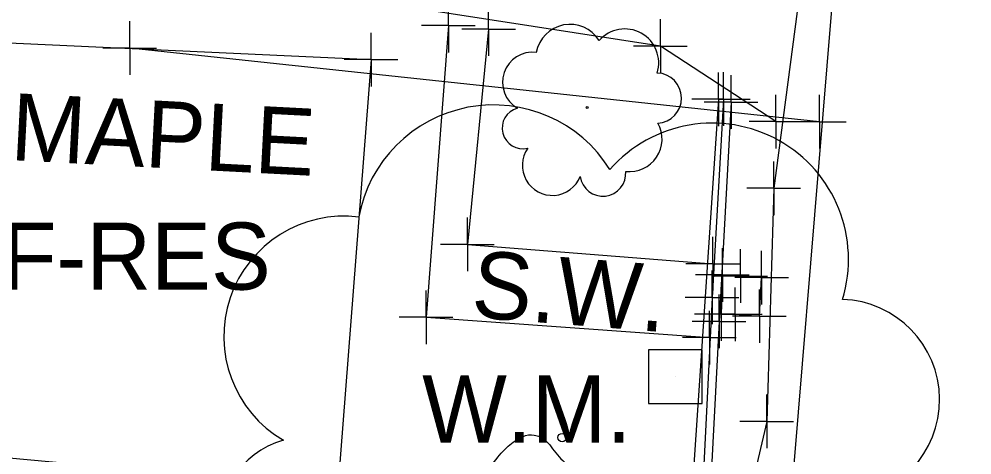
# Model space of a CAD drawing. Extents: x 0 to 1944463, y 0 to 420651.
# Drawn here: x 1943328.1 to 1943399.2, y 417456.9 to 417489.4 of the extents above; entities that cross this region are included whole.
import ezdxf

# ---------------------------------------------------------------- set-up
doc = ezdxf.new("R2010")
doc.units = 0
for name, color, linetype in [('SUR - DTM - Breaklines', 7, 'Continuous'), ('SUR - DTM - Breaklines - Points - Locators', 7, 'Continuous'), ('SUR - NON-TRAN - Buildings', 7, 'Continuous'), ('SUR - NON-TRAN - Buildings - Points - Locators', 7, 'Continuous'), ('SUR - NON-TRAN - Buildings Text', 7, 'Continuous'), ('SUR - NON-TRAN - Features', 7, 'Continuous'), ('SUR - NON-TRAN - Features - Points - Locators', 7, 'Continuous'), ('SUR - NON-TRAN - Features Text', 7, 'Continuous'), ('SUR - PROPERTY - Property Lines', 7, 'Continuous'), ('SUR - TRAN - Features', 7, 'Continuous'), ('SUR - TRAN - Features - Points - Locators', 7, 'Continuous'), ('SUR - TRAN - Roads', 7, 'Continuous'), ('SUR - UTL - Gas', 7, 'Continuous'), ('SUR - UTL - Gas - Points - Locators', 7, 'Continuous'), ('SUR - UTL - Water', 7, 'Continuous'), ('SUR - UTL - Water Text', 7, 'Continuous'), ('SUR - VEG - Features', 7, 'Continuous'), ('SUR - VEG - Features Text', 7, 'Continuous')]:
    doc.layers.add(name, color=color, linetype=linetype)

msp = doc.modelspace()

# ---------------------------------------------------------------- linework, layer by layer
at = {"layer": 'SUR - DTM - Breaklines'}
msp.add_lwpolyline([(1943380.642, 417483.427), (1943379.797, 417468.639), (1943378.803, 417448.68), (1943377.528, 417435.038), (1943376.817, 417428.3), (1943372.837, 417417.332), (1943366.556, 417409.532), (1943358.706, 417403.977), (1943345.201, 417400.148), (1943336.847, 417400.463), (1943331.897, 417401.687), (1943333.202, 417404.643), (1943334.476, 417407.618), (1943330.251, 417411.185), (1943325.276, 417416.517)], dxfattribs=at)
at = {"layer": 'SUR - DTM - Breaklines - Points - Locators'}
for p, q in [((1943380.642, 417483.427), (1943380.642, 417485.427)), ((1943380.642, 417483.427), (1943378.642, 417483.427)), ((1943380.642, 417483.427), (1943382.642, 417483.427)), ((1943380.642, 417483.427), (1943380.642, 417481.427)), ((1943379.797, 417468.639), (1943379.797, 417470.639)), ((1943379.797, 417468.639), (1943377.797, 417468.639)), ((1943379.797, 417468.639), (1943381.797, 417468.639)), ((1943379.797, 417468.639), (1943379.797, 417466.639))]:
    msp.add_line(p, q, dxfattribs=at)
at = {"layer": 'SUR - NON-TRAN - Buildings'}
msp.add_lwpolyline([(1943316.019, 417488.155), (1943354.37, 417486.375), (1943351.907, 417454.397), (1943314.182, 417457.873)], close=True, dxfattribs=at)
at = {"layer": 'SUR - NON-TRAN - Buildings - Points - Locators'}
for q in [(1943354.37, 417488.375), (1943352.37, 417486.375), (1943356.37, 417486.375), (1943354.37, 417484.375)]:
    msp.add_line((1943354.37, 417486.375), q, dxfattribs=at)
at = {"layer": 'SUR - NON-TRAN - Features'}
for points in [[(1943360.144, 417488.914), (1943358.476, 417467.167), (1943379.591, 417465.646)], [(1943363.137, 417488.646), (1943361.555, 417472.59), (1943379.845, 417471.153)], [(1943380.276, 417483.415), (1943377.045, 417435.54)]]:
    msp.add_lwpolyline(points, dxfattribs=at)
msp.add_lwpolyline([(1943380.481, 417467.403), (1943381.521, 417467.388), (1943383.315, 417467.244), (1943383.486, 417470.125), (1943381.918, 417470.238), (1943380.561, 417470.323)], close=True, dxfattribs=at)
at = {"layer": 'SUR - NON-TRAN - Features - Points - Locators'}
for p, q in [((1943360.144, 417488.914), (1943360.144, 417490.914)), ((1943363.137, 417488.646), (1943363.137, 417490.646)), ((1943360.144, 417488.914), (1943358.144, 417488.914)), ((1943360.144, 417488.914), (1943362.144, 417488.914)), ((1943360.144, 417488.914), (1943360.144, 417486.914)), ((1943363.137, 417488.646), (1943361.137, 417488.646)), ((1943363.137, 417488.646), (1943365.137, 417488.646)), ((1943363.137, 417488.646), (1943363.137, 417486.646)), ((1943380.276, 417483.415), (1943380.276, 417485.415)), ((1943380.276, 417483.415), (1943378.276, 417483.415)), ((1943380.276, 417483.415), (1943382.276, 417483.415)), ((1943380.276, 417483.415), (1943380.276, 417481.415)), ((1943361.555, 417472.59), (1943361.555, 417474.59)), ((1943361.555, 417472.59), (1943359.555, 417472.59)), ((1943361.555, 417472.59), (1943363.555, 417472.59)), ((1943361.555, 417472.59), (1943361.555, 417470.59)), ((1943379.845, 417471.153), (1943379.845, 417473.153)), ((1943380.561, 417470.323), (1943380.561, 417472.323)), ((1943381.918, 417470.238), (1943381.918, 417472.238)), ((1943383.486, 417470.125), (1943383.486, 417472.125)), ((1943379.845, 417471.153), (1943377.845, 417471.153)), ((1943379.845, 417471.153), (1943381.845, 417471.153)), ((1943379.845, 417471.153), (1943379.845, 417469.153)), ((1943380.561, 417470.323), (1943378.561, 417470.323)), ((1943381.918, 417470.238), (1943379.918, 417470.238)), ((1943380.561, 417470.323), (1943382.561, 417470.323)), ((1943380.561, 417470.323), (1943380.561, 417468.323)), ((1943383.486, 417470.125), (1943381.486, 417470.125)), ((1943381.918, 417470.238), (1943383.918, 417470.238)), ((1943381.918, 417470.238), (1943381.918, 417468.238)), ((1943383.486, 417470.125), (1943385.486, 417470.125)), ((1943383.486, 417470.125), (1943383.486, 417468.125)), ((1943358.476, 417467.167), (1943358.476, 417469.167)), ((1943380.481, 417467.403), (1943380.481, 417469.403)), ((1943381.521, 417467.388), (1943381.521, 417469.388)), ((1943383.315, 417467.244), (1943383.315, 417469.244)), ((1943379.591, 417465.646), (1943379.591, 417467.646)), ((1943358.476, 417467.167), (1943356.476, 417467.167)), ((1943358.476, 417467.167), (1943360.476, 417467.167)), ((1943358.476, 417467.167), (1943358.476, 417465.167)), ((1943380.481, 417467.403), (1943378.481, 417467.403)), ((1943381.521, 417467.388), (1943379.521, 417467.388)), ((1943380.481, 417467.403), (1943382.481, 417467.403)), ((1943380.481, 417467.403), (1943380.481, 417465.403)), ((1943383.315, 417467.244), (1943381.315, 417467.244)), ((1943381.521, 417467.388), (1943383.521, 417467.388)), ((1943381.521, 417467.388), (1943381.521, 417465.388)), ((1943383.315, 417467.244), (1943385.315, 417467.244)), ((1943383.315, 417467.244), (1943383.315, 417465.244)), ((1943379.591, 417465.646), (1943377.591, 417465.646)), ((1943379.591, 417465.646), (1943381.591, 417465.646)), ((1943379.591, 417465.646), (1943379.591, 417463.646))]:
    msp.add_line(p, q, dxfattribs=at)
at = {"layer": 'SUR - NON-TRAN - Features Text'}
msp.add_open_spline([(1943358.733, 417447.376), (1943364.885, 417461.676), (1943370.847, 417453.152), (1943378.417, 417456.17)], degree=2, dxfattribs=at)
at = {"layer": 'SUR - PROPERTY - Property Lines'}
for p, q in [((1943384.392, 417476.781), (1943384.392, 417478.781)), ((1943384.392, 417476.781), (1943382.392, 417476.781)), ((1943384.392, 417476.781), (1943386.392, 417476.781)), ((1943384.392, 417476.781), (1943384.392, 417474.781)), ((1943383.862, 417459.391), (1943383.862, 417461.391)), ((1943383.862, 417459.391), (1943381.862, 417459.391)), ((1943383.862, 417459.391), (1943385.862, 417459.391)), ((1943383.862, 417459.391), (1943383.862, 417457.391))]:
    msp.add_line(p, q, dxfattribs=at)
at = {"layer": 'SUR - TRAN - Features'}
for points in [[(1943384.554, 417481.747), (1943375.941, 417487.388), (1943318.331, 417496.289), (1943305.868, 417491.574)], [(1943381.209, 417483.206), (1943380.319, 417466.847), (1943379.372, 417448.773), (1943378.142, 417434.863), (1943377.392, 417428.08), (1943373.406, 417417.226), (1943366.92, 417409.033), (1943358.987, 417403.444), (1943345.34, 417399.633), (1943336.89, 417399.84), (1943331.172, 417401.351), (1943333.9, 417407.457), (1943329.758, 417410.84), (1943324.981, 417416.168)]]:
    msp.add_lwpolyline(points, dxfattribs=at)
at = {"layer": 'SUR - TRAN - Features - Points - Locators'}
for p, q in [((1943375.941, 417487.388), (1943375.941, 417489.388)), ((1943375.941, 417487.388), (1943373.941, 417487.388)), ((1943375.941, 417487.388), (1943377.941, 417487.388)), ((1943375.941, 417487.388), (1943375.941, 417485.388)), ((1943381.209, 417483.206), (1943381.209, 417485.206)), ((1943381.209, 417483.206), (1943379.209, 417483.206)), ((1943381.209, 417483.206), (1943383.209, 417483.206)), ((1943381.209, 417483.206), (1943381.209, 417481.206)), ((1943384.554, 417481.747), (1943384.554, 417483.747)), ((1943384.554, 417481.747), (1943382.554, 417481.747)), ((1943384.554, 417481.747), (1943386.554, 417481.747)), ((1943384.554, 417481.747), (1943384.554, 417479.747)), ((1943380.319, 417466.847), (1943380.319, 417468.847)), ((1943380.319, 417466.847), (1943378.319, 417466.847)), ((1943380.319, 417466.847), (1943382.319, 417466.847)), ((1943380.319, 417466.847), (1943380.319, 417464.847))]:
    msp.add_line(p, q, dxfattribs=at)
at = {"layer": 'SUR - TRAN - Roads'}
msp.add_lwpolyline([(1943399.162, 417610.135), (1943393.78, 417561.652), (1943391.448, 417535.786), (1943387.006, 417496.574), (1943384.392, 417476.781), (1943383.862, 417459.391), (1943381.353, 417448.68)], dxfattribs=at)
at = {"layer": 'SUR - UTL - Gas'}
for points in [[(1943380.613, 417418.365), (1943384.689, 417441.465), (1943388.995, 417493.436), (1943390.6, 417521.055), (1943395.849, 417581.366)], [(1943387.787, 417481.741), (1943336.382, 417487.235)]]:
    msp.add_lwpolyline(points, dxfattribs=at)
at = {"layer": 'SUR - UTL - Gas - Points - Locators'}
for p, q in [((1943336.382, 417487.235), (1943336.382, 417489.235)), ((1943336.382, 417487.235), (1943334.382, 417487.235)), ((1943336.382, 417487.235), (1943338.382, 417487.235)), ((1943336.382, 417487.235), (1943336.382, 417485.235)), ((1943387.787, 417481.741), (1943387.787, 417483.741)), ((1943387.787, 417481.741), (1943385.787, 417481.741)), ((1943387.787, 417481.741), (1943389.787, 417481.741)), ((1943387.787, 417481.741), (1943387.787, 417479.741))]:
    msp.add_line(p, q, dxfattribs=at)
at = {"layer": 'SUR - UTL - Water'}
msp.add_line((1943377.049, 417462.732), (1943377.049, 417462.732), dxfattribs=at)
msp.add_lwpolyline([(1943375.049, 417464.732), (1943375.049, 417460.732), (1943379.049, 417460.732), (1943379.049, 417464.732), (1943375.049, 417464.732)], dxfattribs=at)
at = {"layer": 'SUR - VEG - Features'}
for centre, radius in [((1943370.48, 417482.8), 0.0783), ((1943368.62, 417458.19), 0.313)]:
    msp.add_circle(centre, radius, dxfattribs=at)
for centre, radius, start, end in [((1943369.201, 417486.446), 2.556, 31.96825, 169.49248), ((1943373.276, 417486.123), 2.539, 342.86408, 138.70256), ((1943366.417, 417484.686), 2.243, 82.91551, 239.70443), ((1943375.641, 417483.504), 1.872, 273.11698, 88.11726), ((1943363.502, 417472.774), 10.222, 31.96825, 169.49248), ((1943365.685, 417481.263), 1.54, 105.03166, 283.77731), ((1943379.804, 417471.483), 10.156, 342.86408, 138.70256), ((1943373.648, 417480.435), 2.413, 262.95807, 29.80374), ((1943367.886, 417478.486), 2.238, 145.05235, 338.47204), ((1943371.656, 417477.892), 1.703, 187.67102, 4.99016), ((1943352.367, 417465.735), 8.971, 82.91551, 239.70443), ((1943389.262, 417461.006), 7.49, 273.11698, 88.11726), ((1943349.438, 417452.042), 6.158, 105.03166, 283.77731)]:
    msp.add_arc(centre, radius, start, end, dxfattribs=at)

# ---------------------------------------------------------------- texts
at = {"layer": 'SUR - NON-TRAN - Buildings Text'}
msp.add_text('1-F-RES', height=5, dxfattribs=at).set_placement((1943320.896, 417469.222))
at = {"layer": 'SUR - NON-TRAN - Features Text'}
msp.add_text('S.W.', height=5, rotation=355.50718, dxfattribs=at).set_placement((1943361.765, 417467.18))
at = {"layer": 'SUR - UTL - Water Text'}
msp.add_text('W.M.', height=5, dxfattribs=at).set_placement((1943358.184, 417457.819))
at = {"layer": 'SUR - VEG - Features Text'}
msp.add_text('15" MAPLE', height=5, rotation=357.01038, dxfattribs=at).set_placement((1943315.779, 417479.495))

doc.saveas('drawing.dxf')
